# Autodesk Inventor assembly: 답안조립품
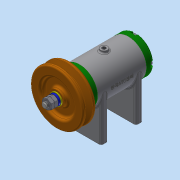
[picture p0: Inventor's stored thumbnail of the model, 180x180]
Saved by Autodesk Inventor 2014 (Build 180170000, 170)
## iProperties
Created: 2020-07
Part Number: 답안조립품
Document SubType Name: Assembly
Designer: kh
Author: kh
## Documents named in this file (15)
- C:\Users\kh\Desktop\700706V1021\답안조립품.iam
- C:\Users\kh\Desktop\700706V1021\본체.ipt
- C:\Users\kh\Desktop\700706V1021\베어링 6002.ipt
- C:\Users\kh\Desktop\700706V1021\뒤커버.ipt
- C:\Users\kh\Desktop\700706V1021\앞커버.ipt
- C:\Users\kh\Desktop\700706V1021\축.ipt
- C:\Users\kh\Desktop\700706V1021\오일 실 15 25 7.ipt
- C:\Users\kh\Desktop\700706V1021\Ű 3x3x12.ipt
- C:\Users\kh\Desktop\700706V1021\V벨트풀리.ipt
- C:\Users\kh\Desktop\700706V1021\와셔 8x17.ipt
- C:\Users\kh\Desktop\700706V1021\스프링와셔 8.ipt
- C:\Users\kh\Desktop\700706V1021\너트 M8.ipt
- C:\Users\kh\Desktop\700706V1021\와셔 6x11.5.ipt
- C:\Users\kh\Desktop\700706V1021\볼트 M6x8.ipt
- C:\Users\kh\Desktop\700706V1021\볼트 M4x12.ipt
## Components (2 placed, 2 different names)
1. Ű 3x3x12:1 — Mate:14, Mate:15, Mate:16, Mate:18, Angle:3
2. V벨트풀리:1 — Mate:17, Mate:18, Mate:19, Mate:21
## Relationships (8: Mate 7, Angle 1)
- Mate:14: Ű 3x3x12:1
- Mate:15: Ű 3x3x12:1
- Mate:16: Ű 3x3x12:1
- Mate:17: V벨트풀리:1
- Mate:18: Ű 3x3x12:1 ↔ V벨트풀리:1
- Mate:19: V벨트풀리:1
- Mate:21: V벨트풀리:1
- Angle:3: Ű 3x3x12:1
